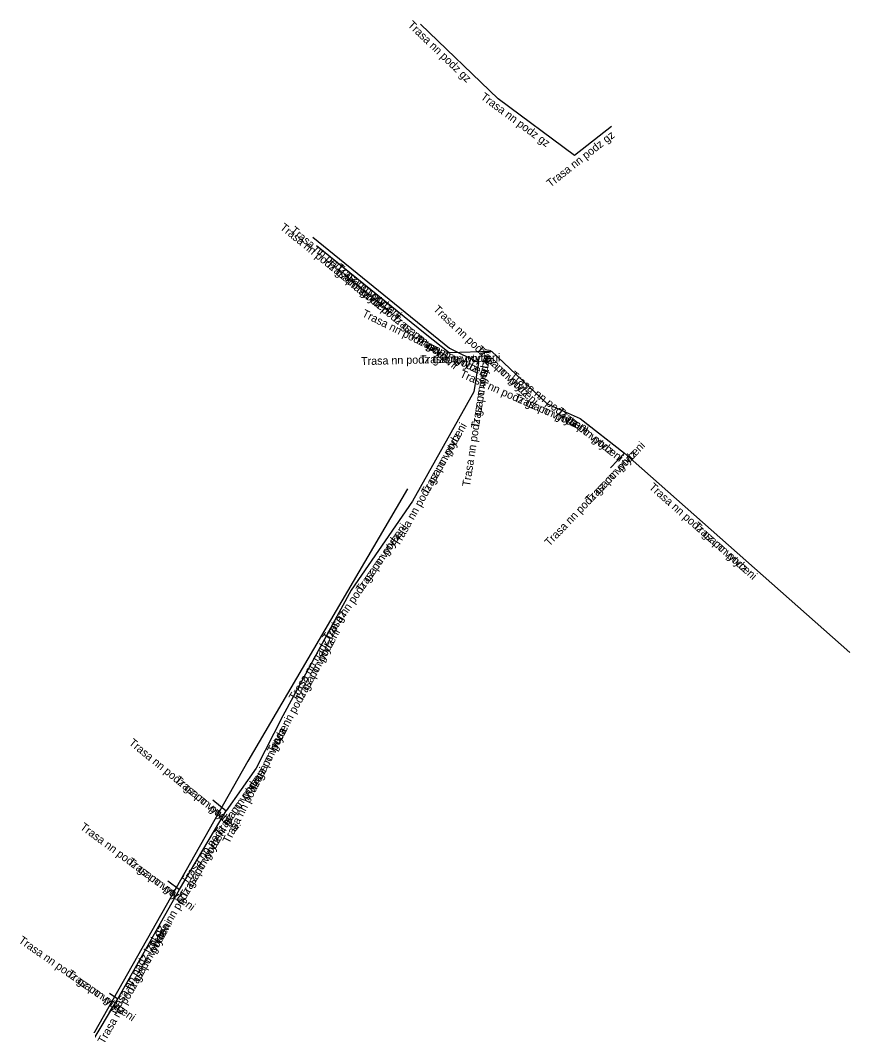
# Model space of a CAD drawing. Extents: x -600654 to -600523, y -1081832 to -1081646.
# Drawn here: x -600597.9 to -600546.1, y -1081708.6 to -1081645.8 of the extents above; entities that cross this region are included whole.
import ezdxf

# ---------------------------------------------------------------- set-up
doc = ezdxf.new("R2010")
doc.units = 0
doc.layers.add('Popiskový text - Ostatní atributy Trasy', color=7, linetype='Continuous')
doc.layers.add('Spojnice NN', color=7, linetype='Continuous')

msp = doc.modelspace()

# ---------------------------------------------------------------- linework, layer by layer
at = {"layer": 'Spojnice NN'}
for points in [[(-600568.1, -1081650.74), (-600572.94, -1081646.08)], [(-600563.32, -1081654.28), (-600568.1, -1081650.74)], [(-600561.02, -1081652.47), (-600563.32, -1081654.28)], [(-600579.651, -1081659.384), (-600571.13, -1081666.32)], [(-600579.651, -1081659.384), (-600571.13, -1081666.32)], [(-600579.42, -1081659.9), (-600572.64, -1081665.39)], [(-600579.42, -1081659.9), (-600572.64, -1081665.39)], [(-600572.64, -1081665.39), (-600571.15, -1081666.58)], [(-600572.64, -1081665.39), (-600571.15, -1081666.58)], [(-600571.15, -1081666.58), (-600568.51, -1081666.51)], [(-600571.15, -1081666.58), (-600568.51, -1081666.51)], [(-600571.13, -1081666.32), (-600569.32, -1081667.22)], [(-600571.13, -1081666.32), (-600569.32, -1081667.22)], [(-600568.51, -1081666.51), (-600565.03, -1081669.8)], [(-600568.51, -1081666.51), (-600565.03, -1081669.8)], [(-600569.32, -1081667.22), (-600569.6, -1081669.05)], [(-600569.32, -1081667.22), (-600569.6, -1081669.05)], [(-600569.6, -1081669.05), (-600573.43, -1081675.86)], [(-600569.6, -1081669.05), (-600573.43, -1081675.86)], [(-600565.03, -1081669.8), (-600562.98, -1081670.7)], [(-600565.03, -1081669.8), (-600562.98, -1081670.7)], [(-600562.98, -1081670.7), (-600560.2, -1081672.87)], [(-600562.98, -1081670.7), (-600560.2, -1081672.87)], [(-600561.08, -1081673.79), (-600560.2, -1081672.87)], [(-600561.08, -1081673.79), (-600560.2, -1081672.87)], [(-600560.2, -1081672.87), (-600546.14, -1081685.32)], [(-600560.2, -1081672.87), (-600546.14, -1081685.32)], [(-600573.74, -1081675.1), (-600583.71, -1081692.11)], [(-600573.43, -1081675.86), (-600577.27, -1081681.43)], [(-600573.43, -1081675.86), (-600577.27, -1081681.43)], [(-600577.27, -1081681.43), (-600581.54, -1081689.27)], [(-600577.27, -1081681.43), (-600581.54, -1081689.27)], [(-600581.54, -1081689.27), (-600583.2, -1081692.54)], [(-600581.54, -1081689.27), (-600583.2, -1081692.54)], [(-600583.71, -1081692.11), (-600596.32, -1081714.4)], [(-600583.2, -1081692.54), (-600585.07, -1081695.2)], [(-600583.2, -1081692.54), (-600585.07, -1081695.2)], [(-600585.9, -1081694.52), (-600585.07, -1081695.2)], [(-600585.9, -1081694.52), (-600585.07, -1081695.2)], [(-600587.98, -1081700.12), (-600585.07, -1081695.2)], [(-600587.98, -1081700.12), (-600585.07, -1081695.2)], [(-600588.71, -1081699.58), (-600587.98, -1081700.12)], [(-600588.71, -1081699.58), (-600587.98, -1081700.12)], [(-600591.83, -1081706.96), (-600587.98, -1081700.12)], [(-600591.83, -1081706.96), (-600587.98, -1081700.12)], [(-600595.96, -1081713.9), (-600591.83, -1081706.96)], [(-600595.96, -1081713.9), (-600591.83, -1081706.96)], [(-600592.36, -1081706.59), (-600591.83, -1081706.96)], [(-600592.36, -1081706.59), (-600591.83, -1081706.96)]]:
    msp.add_lwpolyline(points, dxfattribs=at)

# ---------------------------------------------------------------- texts
at = {"layer": 'Popiskový text - Ostatní atributy Trasy'}
for s, rotation, p in [('Trasa nn podz gz', 316.08547, (-600573.775, -1081646.177)), ('Trasa nn podz gz', 323.47688, (-600569.226, -1081650.715)), ('Trasa nn podz gz', 38.20121, (-600564.828, -1081656.293)), ('Trasa nn podz gz po vytyceni', 321.00171, (-600581.749, -1081658.851)), ('Trasa nn podz gz po vytyceni', 320.85479, (-600581.1, -1081659.043)), ('Trasa nn podz', 321.00171, (-600578.886, -1081661.169)), ('Trasa nn podz', 320.85479, (-600578.242, -1081661.369)), ('Trasa nn podz gz po vytyceni', 321.38712, (-600577.64, -1081662.229)), ('Trasa nn podz gz po vytyceni', 316.60758, (-600572.182, -1081663.934)), ('Trasa nn podz gz po vytyceni', 333.56171, (-600576.632, -1081664.31)), ('Trasa nn podz', 321.38712, (-600574.761, -1081664.529)), ('Trasa nn podz', 333.56171, (-600573.333, -1081665.95)), ('Trasa nn podz', 316.60758, (-600569.504, -1081666.465)), ('Trasa nn podz gz po vytyceni', 1.51885, (-600576.643, -1081667.376)), ('Trasa nn podz', 1.51885, (-600572.959, -1081667.278)), ('Trasa nn podz gz po vytyceni', 81.3009, (-600569.851, -1081674.987)), ('Trasa nn podz', 81.3009, (-600569.294, -1081671.344)), ('Trasa nn podz gz po vytyceni', 336.29735, (-600570.523, -1081668.098)), ('Trasa nn podz gz po vytyceni', 322.02527, (-600567.376, -1081668.093)), ('Trasa nn podz', 336.29735, (-600567.149, -1081669.58)), ('Trasa nn podz', 322.02527, (-600564.471, -1081670.36)), ('Trasa nn podz gz po vytyceni', 60.64624, (-600574.297, -1081678.729)), ('Trasa nn podz', 60.64624, (-600572.491, -1081675.517)), ('Trasa nn podz gz po vytyceni', 46.27303, (-600564.893, -1081678.716)), ('Trasa nn podz', 46.27303, (-600562.346, -1081676.053)), ('Trasa nn podz gz po vytyceni', 318.47541, (-600558.716, -1081675.052)), ('Trasa nn podz gz po vytyceni', 55.41733, (-600578.693, -1081684.639)), ('Trasa nn podz', 318.47541, (-600555.957, -1081677.494)), ('Trasa nn podz', 55.41733, (-600576.602, -1081681.605)), ('Trasa nn nadz izol gz', 59.62433, (-600580.761, -1081688.364)), ('Trasa nn podz gz po vytyceni', 61.4254, (-600582.103, -1081691.661)), ('Trasa nn podz', 61.4254, (-600580.34, -1081688.425)), ('Trasa nn podz gz po vytyceni', 63.08559, (-600584.883, -1081697.292)), ('Trasa nn podz gz po vytyceni', 320.67302, (-600591.182, -1081691.032)), ('Trasa nn podz', 63.08559, (-600583.215, -1081694.006)), ('Trasa nn podz gz po vytyceni', 54.89249, (-600587.533, -1081699.833)), ('Trasa nn podz', 320.67302, (-600588.331, -1081693.368)), ('Trasa nn podz', 54.89249, (-600585.414, -1081696.819)), ('Trasa nn podz gz po vytyceni', 323.5087, (-600594.225, -1081696.31)), ('Trasa nn podz gz po vytyceni', 59.39724, (-600589.444, -1081703.872)), ('Trasa nn podz', 59.39724, (-600587.568, -1081700.7)), ('Trasa nn podz', 323.5087, (-600591.262, -1081698.501)), ('Trasa nn podz gz po vytyceni', 60.62634, (-600592.69, -1081709.813)), ('Trasa nn nadz izol gz', 60.50209, (-600591.978, -1081708.045)), ('Trasa nn podz gz po vytyceni', 325.0806, (-600598.07, -1081703.397)), ('Trasa nn podz', 60.62634, (-600590.882, -1081706.602)), ('Trasa nn podz', 325.0806, (-600595.048, -1081705.506))]:
    msp.add_text(s, height=0.5, rotation=rotation, dxfattribs=at).set_placement(p)

doc.saveas('drawing.dxf')
